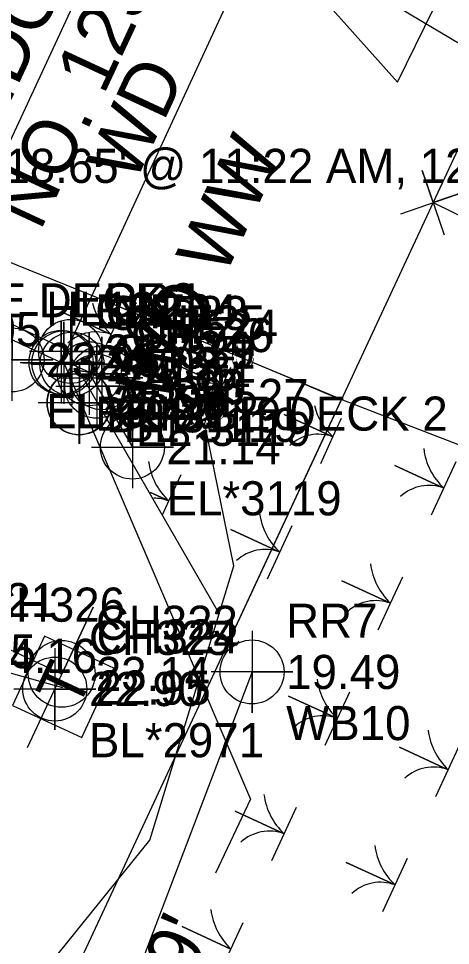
# Model space of a CAD drawing. Extents: x 2532037 to 2533565, y 713396 to 716867.
# Drawn here: x 2532867.9 to 2532899.5, y 715572.7 to 715640.6 of the extents above; entities that cross this region are included whole.
import ezdxf

# ---------------------------------------------------------------- set-up
doc = ezdxf.new("R2010")
doc.units = 0
for name, color, linetype in [('Exist DTM Spot Elevation Cogo Comment', 7, 'Continuous'), ('Exist Environmental Wetland Boundary', 7, 'Continuous'), ('Exist Environmental Wetland Boundary Cogo Comment', 7, 'Continuous'), ('Exist Environmental Wetland Boundary Cogo Elevation', 7, 'Continuous'), ('Exist Environmental Wetland Boundary Cogo Number', 7, 'Continuous'), ('Exist Environmental Wetland Boundary Cogo Point CELL', 7, 'Continuous'), ('Exist Horizontal Alignment', 7, 'Continuous'), ('Exist Hydro Jurisdictional Stream or Body of Water', 7, 'Continuous'), ('Exist Hydro Stream or Body of Water', 7, 'Continuous'), ('Exist Property Corner CELL', 7, 'Continuous'), ('Exist Property Line', 7, 'Continuous'), ('Exist Right of Way Line', 7, 'Continuous'), ('Exist Roads Soil Cogo Comment', 7, 'Continuous'), ('Exist Roads Soil Cogo Elevation', 7, 'Continuous'), ('Exist Roads Soil Cogo Number', 7, 'Continuous'), ('Exist Roads Soil Cogo Point CELL', 7, 'Continuous'), ('Exist Structure Major Bridge Seat Cogo Point CELL', 7, 'Continuous'), ('Exist Structure Major Bridge Seat Leader', 7, 'Continuous'), ('Exist Structure Major Bridge Seat Top Elevation', 7, 'Continuous'), ('Exist Structure Major Bridge WW', 7, 'Continuous'), ('Exist Structure Major Bridge WW Cogo Comment', 7, 'Continuous'), ('Exist Structure Major Bridge WW Cogo Elevation', 7, 'Continuous'), ('Exist Structure Major Bridge WW Cogo Number', 7, 'Continuous'), ('Exist Structure Major Bridge WW Cogo Point CELL', 7, 'Continuous'), ('Exist Structure Major Bridge WW Text', 7, 'Continuous'), ('Exist Structure Major Deck Tunnel Box Culvert', 7, 'Continuous'), ('Exist Structure Major Deck Tunnel Box Culvert Cogo Comment', 7, 'Continuous'), ('Exist Structure Major Deck Tunnel Box Culvert Cogo Elevation', 7, 'Continuous'), ('Exist Structure Major Deck Tunnel Box Culvert Cogo Number', 7, 'Continuous'), ('Exist Structure Major Deck Tunnel Box Culvert Cogo Point CELL', 7, 'Continuous'), ('Exist Structure Major Deck Tunnel Box Culvert Text', 7, 'Continuous'), ('Exist Utilities Power Joint Use Telephone CELL', 7, 'Continuous'), ('Exist Utilities Power Joint Use Telephone Cogo Elevation', 7, 'Continuous'), ('Exist Utilities Power Joint Use Telephone Cogo Number', 7, 'Continuous'), ('Exist Utilities Telephone Pedestal CELL', 7, 'Continuous'), ('Exist Utilities Telephone Pedestal Cogo Elevation', 7, 'Continuous'), ('Exist Utilities Telephone Pedestal Cogo Number', 7, 'Continuous'), ('Exist Utilities Telephone UG Cable SUE LOS B Cogo Comment', 7, 'Continuous'), ('Exist Utilities Telephone UG Cable SUE LOS B Cogo Elevation', 7, 'Continuous'), ('Exist Utilities Telephone UG Cable SUE LOS B Cogo Number', 7, 'Continuous'), ('Exist Utilities Telephone UG Cable SUE LOS B Cogo Point CELL', 7, 'Continuous'), ('Exist Utilities Telephone UG Cable SUE LOS C', 7, 'Continuous'), ('Scratch_Level_1', 7, 'Continuous')]:
    doc.layers.add(name, color=color, linetype=linetype)

msp = doc.modelspace()

# ---------------------------------------------------------------- linework, layer by layer
at = {"layer": 'Exist Environmental Wetland Boundary'}
for p, q in [((2532853.937, 715624.448), (2532871.679, 715616.187)), ((2532883.855, 715594.668), (2532884.001, 715594.986)), ((2532884.968, 715592.701), (2532871.25, 715556.678))]:
    msp.add_line(p, q, dxfattribs=at)
at = {"layer": 'Exist Environmental Wetland Boundary Cogo Point CELL'}
for points in [[(2532871.679, 715619.187), (2532871.679, 715613.187), (2532871.679, 715616.187), (2532874.679, 715616.187), (2532868.679, 715616.187)], [(2532884.968, 715595.701), (2532884.968, 715589.701), (2532884.968, 715592.701), (2532887.968, 715592.701), (2532881.968, 715592.701)]]:
    msp.add_lwpolyline(points, dxfattribs=at)
for centre in [(2532871.679, 715616.187), (2532884.968, 715592.701)]:
    msp.add_circle(centre, 2.344, dxfattribs=at)
at = {"layer": 'Exist Horizontal Alignment'}
msp.add_line((2532720.816, 715316.862), (2532922.836, 715751.084), dxfattribs=at)
at = {"layer": 'Exist Hydro Jurisdictional Stream or Body of Water'}
for points in [[(2532806.944, 715649.86), (2532823.862, 715653.608), (2532826.936, 715654.78), (2532846.795, 715657.486), (2532848.935, 715657.763), (2532859.818, 715661.557), (2532865.255, 715655.34), (2532866.545, 715654.873), (2532867.828, 715654.527), (2532870.349, 715653.031), (2532883.272, 715647.025), (2532884.83, 715646.372), (2532885.882, 715645.762), (2532886.539, 715645.426), (2532889.693, 715644.068), (2532889.952, 715644.137), (2532891.522, 715643.982), (2532891.782, 715643.826), (2532896.496, 715640.921), (2532907.078, 715634.646), (2532915.587, 715630.595), (2532919.574, 715628.211), (2532929.47, 715622.835), (2532946.956, 715616.792)], [(2532799.821, 715621.688), (2532825.866, 715627.44), (2532828.419, 715628.003), (2532832.005, 715633.511), (2532832.017, 715633.527), (2532835.552, 715631.335), (2532845.081, 715630.726), (2532846.796, 715630.623), (2532853.018, 715629.166), (2532854.009, 715628.204), (2532858.784, 715626.141), (2532874.956, 715619.591), (2532887.027, 715614.556), (2532890.708, 715612.987), (2532908.235, 715606.211), (2532911.538, 715604.984), (2532924.18, 715599.711), (2532927.478, 715598.382), (2532943.534, 715592.488)], [(2532883.469, 715595.35), (2532891.527, 715612.67), (2532873.243, 715620.284), (2532871.41, 715616.312), (2532882.562, 715596.954)]]:
    msp.add_lwpolyline(points, dxfattribs=at)
at = {"layer": 'Exist Hydro Stream or Body of Water'}
msp.add_lwpolyline([(2532802.275, 715448.149), (2532818.09, 715482.797), (2532835.704, 715520.842), (2532847.104, 715539.975), (2532855.453, 715551.873), (2532861.069, 715556.637), (2532861.275, 715557.621), (2532865.345, 715565.349), (2532877.493, 715580.363), (2532883.638, 715600.477), (2532881.519, 715610.883), (2532882.285, 715614.354)], dxfattribs=at)
at = {"layer": 'Exist Property Corner CELL'}
msp.add_line((2532898.238, 715627.092), (2532898.238, 715627.092), dxfattribs=at)
msp.add_lwpolyline([(2532895.873, 715626.28), (2532900.602, 715627.904), (2532898.238, 715627.092), (2532897.425, 715629.457), (2532899.05, 715624.728)], dxfattribs=at)
at = {"layer": 'Exist Property Line'}
msp.add_line((2532898.238, 715627.092), (2533035.08, 715560.215), dxfattribs=at)
at = {"layer": 'Exist Right of Way Line'}
msp.add_line((2532748.017, 715304.207), (2532950.036, 715738.429), dxfattribs=at)
at = {"layer": 'Exist Roads Soil Cogo Point CELL'}
msp.add_lwpolyline([(2532867.389, 715612.563), (2532867.389, 715618.563), (2532867.389, 715615.563), (2532870.389, 715615.563), (2532864.389, 715615.563)], dxfattribs=at)
msp.add_circle((2532867.389, 715615.563), 2.344, dxfattribs=at)
at = {"layer": 'Exist Structure Major Bridge Seat Cogo Point CELL'}
msp.add_lwpolyline([(2532868.191, 715615.353), (2532874.191, 715615.353), (2532871.191, 715615.353), (2532871.191, 715618.353), (2532871.191, 715612.353)], dxfattribs=at)
msp.add_lwpolyline([(2532868.191, 715615.353), (2532874.191, 715615.353), (2532871.191, 715615.353), (2532871.191, 715618.353), (2532871.191, 715612.353)], dxfattribs=at)
msp.add_circle((2532871.191, 715615.353), 2.344, dxfattribs=at)
msp.add_circle((2532871.191, 715615.353), 2.344, dxfattribs=at)
at = {"layer": 'Exist Structure Major Bridge Seat Leader'}
for points in [[(2532885.513, 715647.26), (2532895.617, 715635.909), (2532898.253, 715641.299)], [(2532871.191, 715615.353), (2532884.852, 715583.378), (2532882.294, 715577.951)]]:
    msp.add_lwpolyline(points, dxfattribs=at)
at = {"layer": 'Exist Structure Major Bridge WW'}
msp.add_line((2532871.777, 715615.255), (2532873.97, 715614.258), dxfattribs=at)
msp.add_lwpolyline([(2532873.051, 715614.553), (2532873.594, 715613.637), (2532876.206, 715609.174)], dxfattribs=at)
at = {"layer": 'Exist Structure Major Bridge WW Cogo Point CELL'}
for points in [[(2532868.777, 715615.255), (2532874.777, 715615.255), (2532871.777, 715615.255), (2532871.777, 715618.255), (2532871.777, 715612.255)], [(2532870.051, 715614.553), (2532876.051, 715614.553), (2532873.051, 715614.553), (2532873.051, 715617.553), (2532873.051, 715611.553)], [(2532870.97, 715614.258), (2532876.97, 715614.258), (2532873.97, 715614.258), (2532873.97, 715617.258), (2532873.97, 715611.258)], [(2532870.594, 715613.637), (2532876.594, 715613.637), (2532873.594, 715613.637), (2532873.594, 715616.637), (2532873.594, 715610.637)], [(2532873.206, 715609.174), (2532879.206, 715609.174), (2532876.206, 715609.174), (2532876.206, 715612.174), (2532876.206, 715606.174)]]:
    msp.add_lwpolyline(points, dxfattribs=at)
for centre in [(2532871.777, 715615.255), (2532873.051, 715614.553), (2532873.97, 715614.258), (2532873.594, 715613.637), (2532876.206, 715609.174)]:
    msp.add_circle(centre, 2.344, dxfattribs=at)
at = {"layer": 'Exist Structure Major Deck Tunnel Box Culvert'}
msp.add_lwpolyline([(2532885.805, 715647.494), (2532867.812, 715655.999), (2532853.101, 715623.682), (2532870.979, 715615.38), (2532885.805, 715647.494)], dxfattribs=at)
at = {"layer": 'Exist Structure Major Deck Tunnel Box Culvert Cogo Point CELL'}
msp.add_lwpolyline([(2532867.979, 715615.38), (2532873.979, 715615.38), (2532870.979, 715615.38), (2532870.979, 715618.38), (2532870.979, 715612.38)], dxfattribs=at)
msp.add_lwpolyline([(2532867.979, 715615.38), (2532873.979, 715615.38), (2532870.979, 715615.38), (2532870.979, 715618.38), (2532870.979, 715612.38)], dxfattribs=at)
msp.add_circle((2532870.979, 715615.38), 2.344, dxfattribs=at)
msp.add_circle((2532870.979, 715615.38), 2.344, dxfattribs=at)
at = {"layer": 'Exist Utilities Power Joint Use Telephone CELL'}
msp.add_line((2532871.029, 715592.555), (2532871.029, 715592.555), dxfattribs=at)
msp.add_lwpolyline([(2532868.524, 715587.171), (2532873.34, 715597.435), (2532871.046, 715592.546), (2532865.928, 715594.927)], dxfattribs=at)
msp.add_circle((2532871.023, 715592.558), 2.45, dxfattribs=at)
at = {"layer": 'Exist Utilities Telephone Pedestal CELL'}
msp.add_line((2532871.079, 715591.555), (2532871.079, 715591.555), dxfattribs=at)
msp.add_lwpolyline([(2532872.492, 715587.893), (2532874.852, 715592.965), (2532869.779, 715595.325), (2532867.419, 715590.253), (2532872.492, 715587.893)], dxfattribs=at)
at = {"layer": 'Exist Utilities Telephone UG Cable SUE LOS B Cogo Point CELL'}
for points in [[(2532872.298, 715615.425), (2532872.298, 715609.425), (2532872.298, 715612.425), (2532875.298, 715612.425), (2532869.298, 715612.425)], [(2532872.313, 715615.417), (2532872.313, 715609.417), (2532872.313, 715612.417), (2532875.313, 715612.417), (2532869.313, 715612.417)], [(2532872.315, 715615.416), (2532872.315, 715609.416), (2532872.315, 715612.416), (2532875.315, 715612.416), (2532869.315, 715612.416)], [(2532872.323, 715615.414), (2532872.323, 715609.414), (2532872.323, 715612.414), (2532875.323, 715612.414), (2532869.323, 715612.414)], [(2532870.524, 715594.448), (2532870.524, 715588.448), (2532870.524, 715591.448), (2532873.524, 715591.448), (2532867.524, 715591.448)]]:
    msp.add_lwpolyline(points, dxfattribs=at)
for centre in [(2532872.298, 715612.425), (2532872.313, 715612.417), (2532872.315, 715612.416), (2532872.323, 715612.414), (2532870.524, 715591.448)]:
    msp.add_circle(centre, 2.344, dxfattribs=at)
at = {"layer": 'Exist Utilities Telephone UG Cable SUE LOS C'}
msp.add_lwpolyline([(2532724.197, 715351.236), (2532725.333, 715353.656), (2532742.383, 715388.998), (2532760.472, 715427.703), (2532775.735, 715460.821), (2532792.08, 715495.897), (2532810.221, 715535.082), (2532832.169, 715581.195), (2532835.867, 715586.711), (2532839.766, 715591.394), (2532844.317, 715594.265), (2532854.857, 715595.716), (2532862.758, 715593.881), (2532871.079, 715591.555), (2532871.079, 715591.555)], dxfattribs=at)
at = {"layer": 'Scratch_Level_1'}
for points in [[(2532873.753, 715615.468), (2532874.654, 715617.421), (2532871.072, 715619.074), (2532874.654, 715617.421), (2532875.288, 715618.794)], [(2532881.874, 715611.719), (2532882.775, 715613.671), (2532879.194, 715615.325), (2532882.775, 715613.671), (2532883.41, 715615.045)], [(2532889.996, 715607.97), (2532890.897, 715609.922), (2532887.315, 715611.576), (2532890.897, 715609.922), (2532891.531, 715611.296)], [(2532898.117, 715604.22), (2532899.018, 715606.173), (2532895.436, 715607.826), (2532899.018, 715606.173), (2532899.92, 715608.125)], [(2532877.528, 715605.85), (2532878.877, 715605.227), (2532879.778, 715607.179)], [(2532878.429, 715604.257), (2532878.877, 715605.227), (2532877.528, 715605.85)], [(2532886.097, 715599.525), (2532886.998, 715601.478), (2532883.417, 715603.131), (2532886.998, 715601.478), (2532887.9, 715603.43)], [(2532894.219, 715595.776), (2532895.12, 715597.728), (2532891.538, 715599.382), (2532895.12, 715597.728), (2532896.021, 715599.681)], [(2532890.32, 715587.331), (2532891.221, 715589.284), (2532887.64, 715590.937), (2532891.221, 715589.284), (2532892.123, 715591.236)], [(2532898.442, 715583.582), (2532899.343, 715585.534), (2532895.761, 715587.188), (2532899.343, 715585.534), (2532900.244, 715587.487)], [(2532886.422, 715578.887), (2532887.323, 715580.839), (2532883.741, 715582.493), (2532887.323, 715580.839), (2532888.224, 715582.792)], [(2532894.543, 715575.138), (2532895.444, 715577.09), (2532891.863, 715578.744), (2532895.444, 715577.09), (2532896.346, 715579.042)], [(2532882.523, 715570.443), (2532883.425, 715572.395), (2532879.843, 715574.049), (2532883.425, 715572.395), (2532884.326, 715574.347)]]:
    msp.add_lwpolyline(points, dxfattribs=at)
for centre, radius, start, end in [((2532877.941, 715620.926), 4.806, 194.57714, 226.84116), ((2532873.57, 715614.543), 3.075, 69.35932, 132.75394), ((2532886.063, 715617.177), 4.806, 194.57714, 226.84116), ((2532881.692, 715610.794), 3.075, 69.35932, 132.75394), ((2532894.184, 715613.427), 4.806, 194.57714, 226.84116), ((2532889.813, 715607.045), 3.075, 69.35932, 132.75394), ((2532902.306, 715609.678), 4.806, 187.34643, 226.84116), ((2532882.164, 715608.732), 4.806, 187.34643, 226.84116), ((2532897.935, 715603.295), 3.075, 69.35932, 132.75394), ((2532877.793, 715602.35), 3.075, 69.35932, 90.45296), ((2532890.286, 715604.983), 4.806, 187.34643, 226.84116), ((2532885.915, 715598.6), 3.075, 69.35932, 132.75394), ((2532898.407, 715601.234), 4.806, 187.34643, 226.84116), ((2532894.036, 715594.851), 3.075, 69.35932, 132.75394), ((2532894.509, 715592.789), 4.806, 187.34643, 226.84116), ((2532890.138, 715586.407), 3.075, 69.35932, 132.75394), ((2532902.63, 715589.04), 4.806, 187.34643, 226.84116), ((2532898.259, 715582.657), 3.075, 69.35932, 132.75394), ((2532890.61, 715584.345), 4.806, 187.34643, 226.84116), ((2532886.239, 715577.962), 3.075, 69.35932, 132.75394), ((2532898.732, 715580.596), 4.806, 187.34643, 226.84116), ((2532894.361, 715574.213), 3.075, 69.35932, 132.75394), ((2532886.712, 715575.901), 4.806, 187.34643, 226.84116)]:
    msp.add_arc(centre, radius, start, end, dxfattribs=at)

# ---------------------------------------------------------------- texts
at = {"layer": 'Exist DTM Spot Elevation Cogo Comment'}
msp.add_text("TOP OF WATER EL: 18.65' @ 11:22 AM, 12-6-18", height=2.5, dxfattribs=at).set_placement((2532834.511, 715628.536))
at = {"layer": 'Exist Environmental Wetland Boundary Cogo Comment'}
for s, p in [('WB9', (2532874.179, 715611.187)), ('WB10', (2532887.468, 715587.701))]:
    msp.add_text(s, height=2.5, dxfattribs=at).set_placement(p)
at = {"layer": 'Exist Environmental Wetland Boundary Cogo Elevation'}
for s, p in [('24.78', (2532874.179, 715614.937)), ('19.49', (2532887.468, 715591.451))]:
    msp.add_text(s, height=2.5, dxfattribs=at).set_placement(p)
at = {"layer": 'Exist Environmental Wetland Boundary Cogo Number'}
for s, p in [('RR3', (2532874.179, 715618.687)), ('RR7', (2532887.468, 715595.201))]:
    msp.add_text(s, height=2.5, dxfattribs=at).set_placement(p)
at = {"layer": 'Exist Roads Soil Cogo Comment'}
for s, p in [('BL*3005', (2532856.708, 715616.565)), ('EL*3005', (2532869.889, 715610.563))]:
    msp.add_text(s, height=2.5, dxfattribs=at).set_placement(p)
at = {"layer": 'Exist Roads Soil Cogo Elevation'}
for s, p in [('23.96', (2532869.889, 715614.313)), ('24.25', (2532860.769, 715592.966))]:
    msp.add_text(s, height=2.5, dxfattribs=at).set_placement(p)
at = {"layer": 'Exist Roads Soil Cogo Number'}
for s, p in [('HL122', (2532869.889, 715618.063)), ('HL121', (2532860.769, 715596.716))]:
    msp.add_text(s, height=2.5, dxfattribs=at).set_placement(p)
at = {"layer": 'Exist Structure Major Bridge Seat Top Elevation'}
msp.add_text("BS2=21.99'", height=4, rotation=65.05, dxfattribs=at).set_placement((2532870.557, 715548.591))
at = {"layer": 'Exist Structure Major Bridge WW Cogo Comment'}
for s, p in [('BL*3119', (2532874.277, 715610.255)), ('BL*3119', (2532875.551, 715609.553)), ('EL*3119', (2532876.47, 715609.258)), ('EL*3119', (2532878.706, 715604.174))]:
    msp.add_text(s, height=2.5, dxfattribs=at).set_placement(p)
at = {"layer": 'Exist Structure Major Bridge WW Cogo Elevation'}
for s, p in [('24.03', (2532874.277, 715614.005)), ('24.05', (2532875.551, 715613.303)), ('23.93', (2532876.094, 715612.387)), ('24.04', (2532876.47, 715613.008)), ('21.14', (2532878.706, 715607.924))]:
    msp.add_text(s, height=2.5, dxfattribs=at).set_placement(p)
at = {"layer": 'Exist Structure Major Bridge WW Cogo Number'}
for s, p in [('CH523', (2532874.277, 715617.755)), ('CH525', (2532875.551, 715617.053)), ('CH524', (2532876.47, 715616.758)), ('CH526', (2532876.094, 715616.137)), ('CH527', (2532878.706, 715611.674))]:
    msp.add_text(s, height=2.5, dxfattribs=at).set_placement(p)
at = {"layer": 'Exist Structure Major Bridge WW Text'}
msp.add_text('WD WW', height=4, rotation=65.05, dxfattribs=at).set_placement((2532878.559, 715612.132))
at = {"layer": 'Exist Structure Major Deck Tunnel Box Culvert Cogo Comment'}
for s, p in [('BRIDGE DECK 1', (2532855.601, 715618.682)), ('BRIDGE DECK 2', (2532873.479, 715610.38))]:
    msp.add_text(s, height=2.5, dxfattribs=at).set_placement(p)
at = {"layer": 'Exist Structure Major Deck Tunnel Box Culvert Cogo Elevation'}
msp.add_text('24.03', height=2.5, dxfattribs=at).set_placement((2532873.479, 715614.13))
msp.add_text('24.03', height=2.5, dxfattribs=at).set_placement((2532873.479, 715614.13))
at = {"layer": 'Exist Structure Major Deck Tunnel Box Culvert Cogo Number'}
for s in ['CH504', 'BD2']:
    msp.add_text(s, height=2.5, dxfattribs=at).set_placement((2532873.479, 715617.88))
at = {"layer": 'Exist Structure Major Deck Tunnel Box Culvert Text'}
for s, p in [('BRIDGE', (2532864, 715627.432)), ('NO. 123', (2532869.46, 715624.944)), ('WD', (2532876.352, 715628.373))]:
    msp.add_text(s, height=4, rotation=65.05, dxfattribs=at).set_placement(p)
at = {"layer": 'Exist Utilities Power Joint Use Telephone Cogo Elevation'}
msp.add_text('23.14', height=2.5, dxfattribs=at).set_placement((2532873.529, 715591.305))
at = {"layer": 'Exist Utilities Power Joint Use Telephone Cogo Number'}
msp.add_text('CH323', height=2.5, dxfattribs=at).set_placement((2532873.529, 715595.055))
at = {"layer": 'Exist Utilities Telephone Pedestal CELL'}
msp.add_text('T', height=3.42, rotation=65.05, dxfattribs=at).set_placement((2532872.155, 715589.807))
at = {"layer": 'Exist Utilities Telephone Pedestal Cogo Elevation'}
msp.add_text('22.95', height=2.5, dxfattribs=at).set_placement((2532873.579, 715590.305))
at = {"layer": 'Exist Utilities Telephone Pedestal Cogo Number'}
msp.add_text('CH324', height=2.5, dxfattribs=at).set_placement((2532873.579, 715594.055))
at = {"layer": 'Exist Utilities Telephone UG Cable SUE LOS B Cogo Comment'}
msp.add_text('BL*2971', height=2.5, dxfattribs=at).set_placement((2532873.024, 715586.448))
at = {"layer": 'Exist Utilities Telephone UG Cable SUE LOS B Cogo Elevation'}
for s, p in [('25.29', (2532874.798, 715611.175)), ('25.27', (2532874.813, 715611.167)), ('25.28', (2532874.815, 715611.166)), ('25.20', (2532874.823, 715611.164)), ('24.16', (2532865.258, 715592.631)), ('22.90', (2532873.024, 715590.198))]:
    msp.add_text(s, height=2.5, dxfattribs=at).set_placement(p)
at = {"layer": 'Exist Utilities Telephone UG Cable SUE LOS B Cogo Number'}
for s, p in [('CH329', (2532874.798, 715614.925)), ('CH331', (2532874.813, 715614.917)), ('CH330', (2532874.815, 715614.916)), ('CH328', (2532874.823, 715614.914)), ('CH326', (2532865.258, 715596.381)), ('CH325', (2532873.024, 715593.948))]:
    msp.add_text(s, height=2.5, dxfattribs=at).set_placement(p)

doc.saveas('drawing.dxf')
